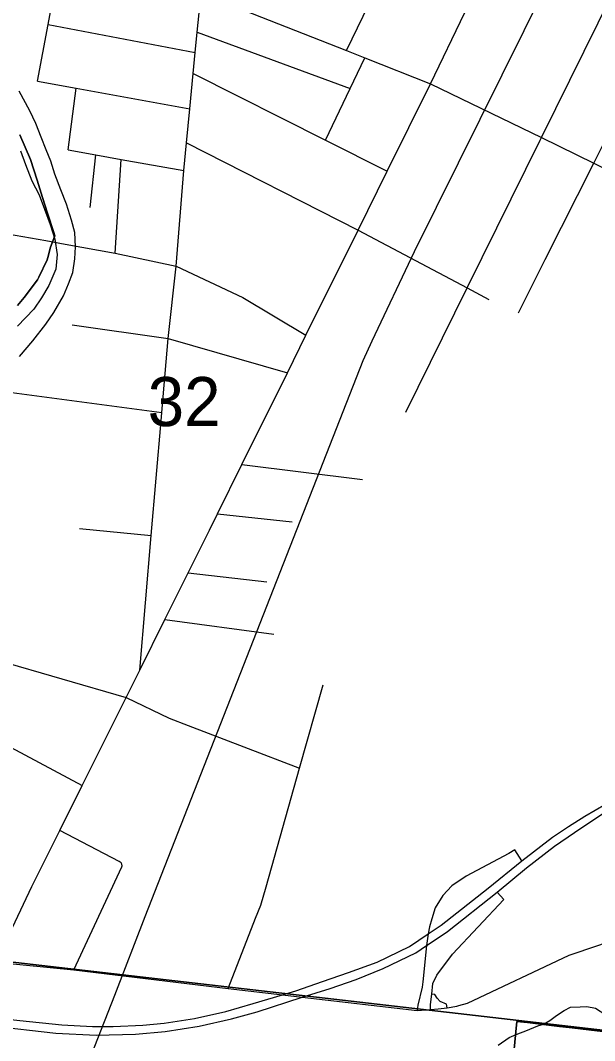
# Model space of a CAD drawing. Extents: x 0 to 34, y -3.9 to 26.2.
# Drawn here: x 3.391 to 3.881, y 18.269 to 19.139 of the extents above; entities that cross this region are included whole.
import ezdxf

# ---------------------------------------------------------------- set-up
doc = ezdxf.new("R2010")
doc.units = 0
for name, color, linetype in [('GM_X_City_Street', 7, 'Continuous'), ('GM_X_Corporation', 7, 'Continuous'), ('GM_X_County_Road', 7, 'Continuous'), ('GM_X_Interchange_Ramps', 7, 'Continuous'), ('GM_X_Minor_River', 7, 'Continuous'), ('GM_X_Rail_Line', 7, 'Continuous'), ('GM_X_Section', 7, 'Continuous'), ('GM_X_Section_Text', 7, 'Continuous'), ('GM_X_State_Route', 7, 'Continuous'), ('GM_X_US_Route', 7, 'Continuous')]:
    doc.layers.add(name, color=color, linetype=linetype)

msp = doc.modelspace()

# ---------------------------------------------------------------- linework, layer by layer
at = {"layer": 'GM_X_City_Street'}
for p, q in [((3.41438, 19.1356), (3.54001, 19.11187)), ((3.5417, 19.12917), (3.67244, 19.08113)), ((3.43152, 19.02861), (3.43815, 19.08141)), ((3.45036, 18.97951), (3.45516, 19.0244)), ((3.47157, 18.94054), (3.47661, 19.02057)), ((3.81594, 18.88965), (3.83878, 18.93501)), ((3.71971, 18.80489), (3.77214, 18.91084)), ((3.3792, 18.82232), (3.51145, 18.80468)), ((3.5799, 18.76025), (3.68297, 18.7474)), ((3.55907, 18.71824), (3.62288, 18.71142)), ((3.44107, 18.70563), (3.50246, 18.6997)), ((3.53395, 18.66779), (3.60109, 18.65998)), ((3.51404, 18.62784), (3.60706, 18.61548)), ((3.28562, 18.6179), (3.48091, 18.56138))]:
    msp.add_line(p, q, dxfattribs=at)
for points in [[(3.66913, 19.11339), (3.68339, 19.14274), (3.69722, 19.17116), (3.71933, 19.21662), (3.73336, 19.24545), (3.75568, 19.29136), (3.76214, 19.30462), (3.76431, 19.30909)], [(3.83878, 18.93501), (3.88028, 19.01742), (3.91032, 19.07708), (3.94313, 19.14226), (3.94384, 19.14366), (3.96986, 19.19533), (4.00778, 19.27066)], [(3.40534, 19.0874), (3.41438, 19.1356), (3.42359, 19.18468)], [(3.49261, 18.58485), (3.50246, 18.6997), (3.51084, 18.79758), (3.51145, 18.80468), (3.51345, 18.82796), (3.51685, 18.86761), (3.52366, 18.92952), (3.53016, 19.01103), (3.53247, 19.03461), (3.53531, 19.0637), (3.53825, 19.09381), (3.54001, 19.11187), (3.5417, 19.12917), (3.54493, 19.16227)], [(3.83562, 19.03913), (3.89645, 19.16207), (3.89772, 19.16464)], [(3.6513, 19.03707), (3.67244, 19.08113), (3.68493, 19.10718)], [(3.53825, 19.09381), (3.6513, 19.03707), (3.70403, 19.01061)], [(3.40534, 19.0874), (3.43815, 19.08141), (3.53531, 19.0637)], [(3.77214, 18.91084), (3.77273, 18.91205), (3.8346, 19.03706), (3.83562, 19.03913)], [(3.53247, 19.03461), (3.679, 18.96013), (3.77214, 18.91084), (3.79082, 18.90095)], [(3.43152, 19.02861), (3.45516, 19.0244), (3.47661, 19.02057), (3.53016, 19.01103)], [(3.42879, 18.94834), (3.47157, 18.94054), (3.52366, 18.92952), (3.58051, 18.90271), (3.63453, 18.87045)], [(3.43489, 18.87931), (3.51685, 18.86761), (3.61866, 18.83843)], [(3.25178, 18.65954), (3.2609, 18.65098), (3.2687, 18.64376), (3.27479, 18.63634), (3.28562, 18.6179), (3.2919, 18.59413), (3.30072, 18.57156), (3.30994, 18.56144), (3.32406, 18.55005), (3.33454, 18.54446), (3.38229, 18.51898), (3.44349, 18.48632)], [(3.56805, 18.3131), (3.59147, 18.37321), (3.59592, 18.38411), (3.6005, 18.39993), (3.62914, 18.50103), (3.64928, 18.57213)], [(3.48091, 18.56138), (3.5177, 18.54375), (3.53385, 18.53763), (3.62914, 18.50103)], [(3.4364, 18.32913), (3.47729, 18.41688), (3.47751, 18.4178), (3.47735, 18.41916), (3.47676, 18.42018), (3.47595, 18.42083), (3.47513, 18.42149), (3.42431, 18.44785)]]:
    msp.add_lwpolyline(points, dxfattribs=at)
at = {"layer": 'GM_X_Corporation'}
for points in [[(3.38812, 18.89583), (3.39388, 18.90258), (3.40527, 18.91772), (3.40642, 18.92013), (3.41343, 18.93481), (3.41399, 18.93689), (3.41631, 18.9456), (3.42017, 18.95525), (3.41891, 18.95917), (3.41392, 18.97473), (3.40963, 18.98812), (3.40491, 19.00284), (3.39922, 19.02059), (3.39027, 19.04149)], [(3.39027, 19.04149), (3.39922, 19.02059), (3.40491, 19.00284), (3.40963, 18.98812), (3.41392, 18.97473), (3.41891, 18.95917), (3.42017, 18.95525), (3.41631, 18.9456), (3.41399, 18.93689), (3.41343, 18.93481), (3.40642, 18.92013), (3.40527, 18.91772), (3.39388, 18.90258), (3.38812, 18.89583)], [(3.81079, 18.24369), (3.81469, 18.28506), (3.82386, 18.28399), (3.85122, 18.28078), (3.8618, 18.27954), (3.88323, 18.27703), (3.91823, 18.27293), (3.94703, 18.26903), (3.97417, 18.26561)], [(3.97417, 18.26561), (3.94703, 18.26903), (3.91823, 18.27293), (3.88323, 18.27703), (3.8618, 18.27954), (3.85122, 18.28078), (3.82386, 18.28399), (3.81469, 18.28506), (3.81079, 18.24369)]]:
    msp.add_lwpolyline(points, dxfattribs=at)
at = {"layer": 'GM_X_County_Road'}
msp.add_line((3.41244, 18.95125), (3.42879, 18.94834), dxfattribs=at)
for points in [[(3.36715, 19.19868), (3.39229, 19.19223), (3.42359, 19.18468), (3.4673, 19.17661), (3.54493, 19.16227), (3.66913, 19.11339), (3.68493, 19.10718), (3.74097, 19.08512), (3.83562, 19.03913), (3.88028, 19.01742), (3.88909, 19.01315)], [(3.19711, 18.96732), (3.23986, 18.96721), (3.31357, 18.96963), (3.32194, 18.97077), (3.35616, 18.96279), (3.37974, 18.95708), (3.41244, 18.95125)], [(3.76523, 18.29845), (3.77257, 18.30043), (3.85927, 18.3416), (3.88385, 18.34978), (3.91385, 18.36018), (3.97632, 18.37695), (3.99112, 18.37843), (4.0023, 18.37826), (4.01397, 18.37613), (4.02121, 18.37333), (4.02729, 18.37037), (4.03353, 18.36594), (4.03765, 18.36248), (4.0411, 18.35706), (4.0434, 18.35229), (4.04583, 18.34194), (4.04965, 18.3035), (4.05067, 18.29972), (4.05218, 18.29699), (4.05721, 18.29327), (4.09075, 18.27748), (4.1427, 18.25266)], [(3.36974, 18.3356), (3.4364, 18.32913), (3.56805, 18.3131), (3.61441, 18.30775), (3.63117, 18.30581), (3.72945, 18.29417), (3.74088, 18.29516), (3.74757, 18.2956), (3.75516, 18.2965), (3.7634, 18.29795), (3.76523, 18.29845)]]:
    msp.add_lwpolyline(points, dxfattribs=at)
at = {"layer": 'GM_X_Interchange_Ramps'}
for points in [[(3.819, 18.42209), (3.81292, 18.43127), (3.80775, 18.42827), (3.77136, 18.40882), (3.75922, 18.40059), (3.75148, 18.39254), (3.74486, 18.38202), (3.7421, 18.37258), (3.74012, 18.36567), (3.73896, 18.35974), (3.73752, 18.34979), (3.73429, 18.31878)], [(3.74088, 18.29516), (3.74097, 18.29936), (3.74195, 18.30837), (3.74293, 18.31738), (3.74632, 18.32453), (3.75972, 18.34238), (3.80363, 18.38915), (3.79799, 18.39515)], [(3.73429, 18.31878), (3.73383, 18.31435), (3.73009, 18.299), (3.72945, 18.29417)], [(3.75516, 18.2965), (3.75453, 18.29971), (3.74918, 18.30185), (3.74668, 18.30489), (3.74454, 18.3081), (3.74195, 18.30837)]]:
    msp.add_lwpolyline(points, dxfattribs=at)
at = {"layer": 'GM_X_Minor_River'}
for points in [[(3.38997, 18.85231), (3.40123, 18.86578), (3.4125, 18.88002), (3.41913, 18.88978), (3.42737, 18.90407), (3.43173, 18.91425), (3.43533, 18.92407), (3.43707, 18.93582), (3.43764, 18.94607), (3.43711, 18.95825), (3.43427, 18.96857), (3.42997, 18.98233), (3.42527, 18.99459), (3.42021, 19.00799), (3.41663, 19.01908), (3.41263, 19.02866), (3.40828, 19.03939), (3.40395, 19.05125), (3.39884, 19.062), (3.38967, 19.0789)], [(3.39061, 19.02794), (3.39494, 19.01607), (3.40037, 19.00228), (3.4066, 18.99038), (3.4113, 18.97812), (3.41599, 18.96511), (3.41993, 18.95249), (3.42196, 18.93953), (3.42097, 18.927), (3.41501, 18.91304), (3.40875, 18.90252), (3.40211, 18.89276), (3.38818, 18.8782)], [(3.8325, 18.28122), (3.83749, 18.28253), (3.84294, 18.28573), (3.84843, 18.29006), (3.85506, 18.29435), (3.86049, 18.29716), (3.86887, 18.29757), (3.87458, 18.29772), (3.88174, 18.29628), (3.89063, 18.29059), (3.89502, 18.28623), (3.89979, 18.28185), (3.90611, 18.27817), (3.91131, 18.27529), (3.921, 18.27033), (3.92911, 18.26391)], [(3.79879, 18.26475), (3.80817, 18.2712), (3.81551, 18.27432), (3.82246, 18.27707), (3.8325, 18.28122)]]:
    msp.add_lwpolyline(points, dxfattribs=at)
at = {"layer": 'GM_X_Rail_Line'}
msp.add_lwpolyline([(3.37651, 18.06594), (3.47122, 18.30729), (3.49729, 18.3746), (3.58974, 18.6102), (3.68343, 18.84909), (3.69102, 18.86587), (3.72714, 18.94195), (3.82083, 19.13046), (3.8785, 19.24774)], dxfattribs=at)
at = {"layer": 'GM_X_Section'}
for points in [[(3.06078, 19.39362), (4.07507, 19.26688), (3.97441, 18.26756), (2.95688, 18.38489)], [(2.95688, 18.38489), (3.97441, 18.26756), (3.88035, 17.25787), (2.86031, 17.36388)]]:
    msp.add_lwpolyline(points, close=True, dxfattribs=at)
at = {"layer": 'GM_X_State_Route'}
for points in [[(3.36566, 18.28122), (3.42099, 18.275), (3.45542, 18.27324), (3.48898, 18.27412), (3.51442, 18.27632), (3.54338, 18.28092), (3.57101, 18.28728), (3.59294, 18.2932), (3.63117, 18.30581), (3.65523, 18.31316), (3.67739, 18.32084), (3.70063, 18.33005), (3.72827, 18.34365), (3.73752, 18.34979), (3.74671, 18.35585), (3.75547, 18.36163), (3.79799, 18.39515), (3.82302, 18.41603), (3.84693, 18.43467), (3.86382, 18.4463), (3.89054, 18.464), (3.91224, 18.47628)], [(3.819, 18.42209), (3.84521, 18.44216), (3.85864, 18.45142), (3.87275, 18.46022), (3.89033, 18.47045)], [(3.11101, 18.31672), (3.13346, 18.31457), (3.16778, 18.31065), (3.35193, 18.29015), (3.39008, 18.28583), (3.42616, 18.28211), (3.45226, 18.28057), (3.4698, 18.28068), (3.49535, 18.28189), (3.51334, 18.28342), (3.53944, 18.28759), (3.56609, 18.29351), (3.58945, 18.3002), (3.61441, 18.30775), (3.62584, 18.31121), (3.64877, 18.31906), (3.67093, 18.32663), (3.6953, 18.33544), (3.72294, 18.34904), (3.73896, 18.35974), (3.75013, 18.36703), (3.79018, 18.39859), (3.819, 18.42209)]]:
    msp.add_lwpolyline(points, dxfattribs=at)
at = {"layer": 'GM_X_US_Route'}
msp.add_lwpolyline([(3.37412, 18.34478), (3.40056, 18.40021), (3.42431, 18.44785), (3.44349, 18.48632), (3.48091, 18.56138), (3.49261, 18.58485), (3.51404, 18.62784), (3.53395, 18.66779), (3.55209, 18.70417), (3.55907, 18.71824), (3.5799, 18.76025), (3.61866, 18.83843), (3.63453, 18.87045), (3.679, 18.96013), (3.70403, 19.01061), (3.74097, 19.08512), (3.77016, 19.14597)], dxfattribs=at)

# ---------------------------------------------------------------- texts
at = {"layer": 'GM_X_Section_Text'}
msp.add_text('32', height=0.041856, rotation=0.00001, dxfattribs=at).set_placement((3.49936, 18.793))

doc.saveas('drawing.dxf')
